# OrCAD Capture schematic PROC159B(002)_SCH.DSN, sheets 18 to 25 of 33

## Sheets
18 01. TABLE OF CONTENTS: title: TABLE OF CONTENTS
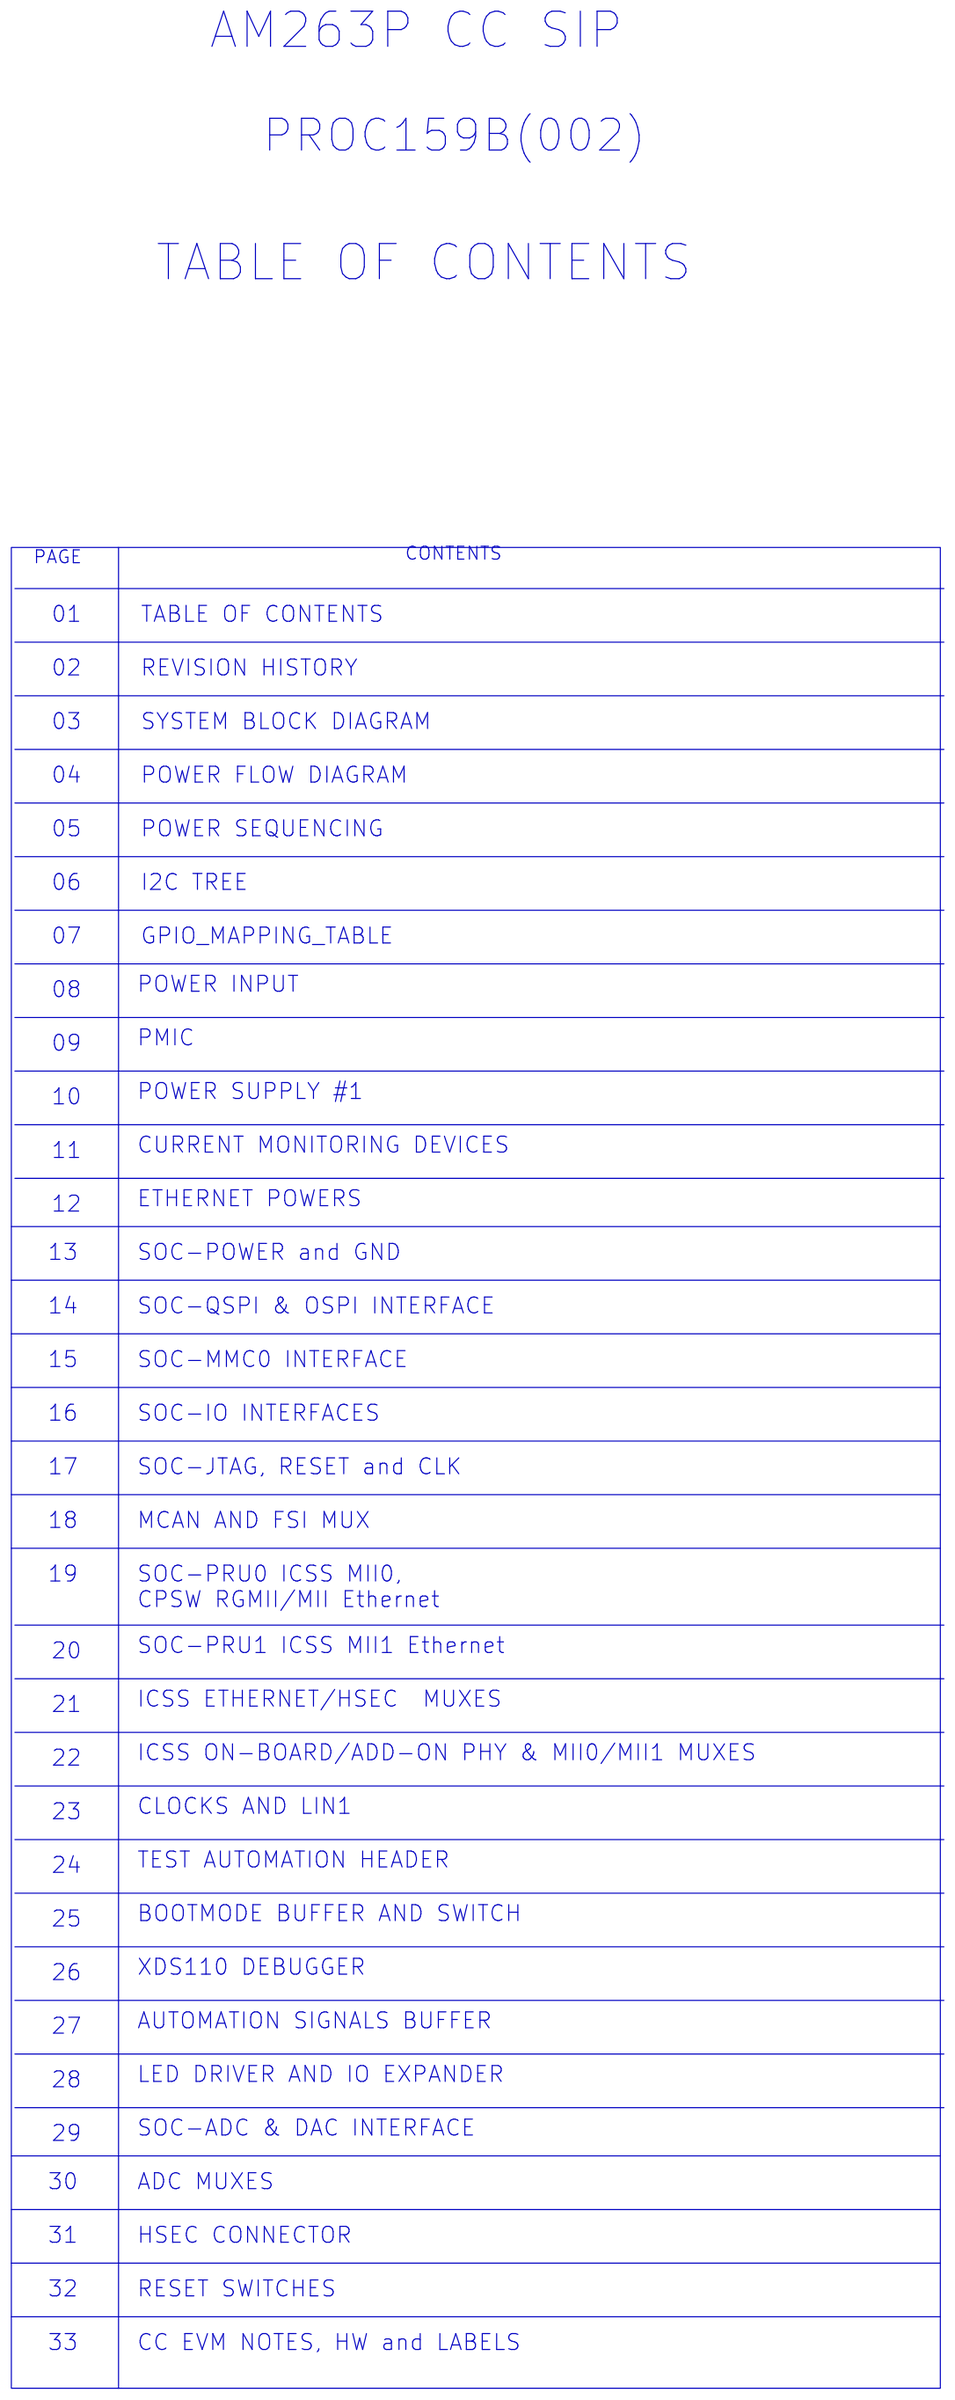
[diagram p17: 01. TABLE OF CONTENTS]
19 02. REVISION HISTORY: title: REVISION HISTORY
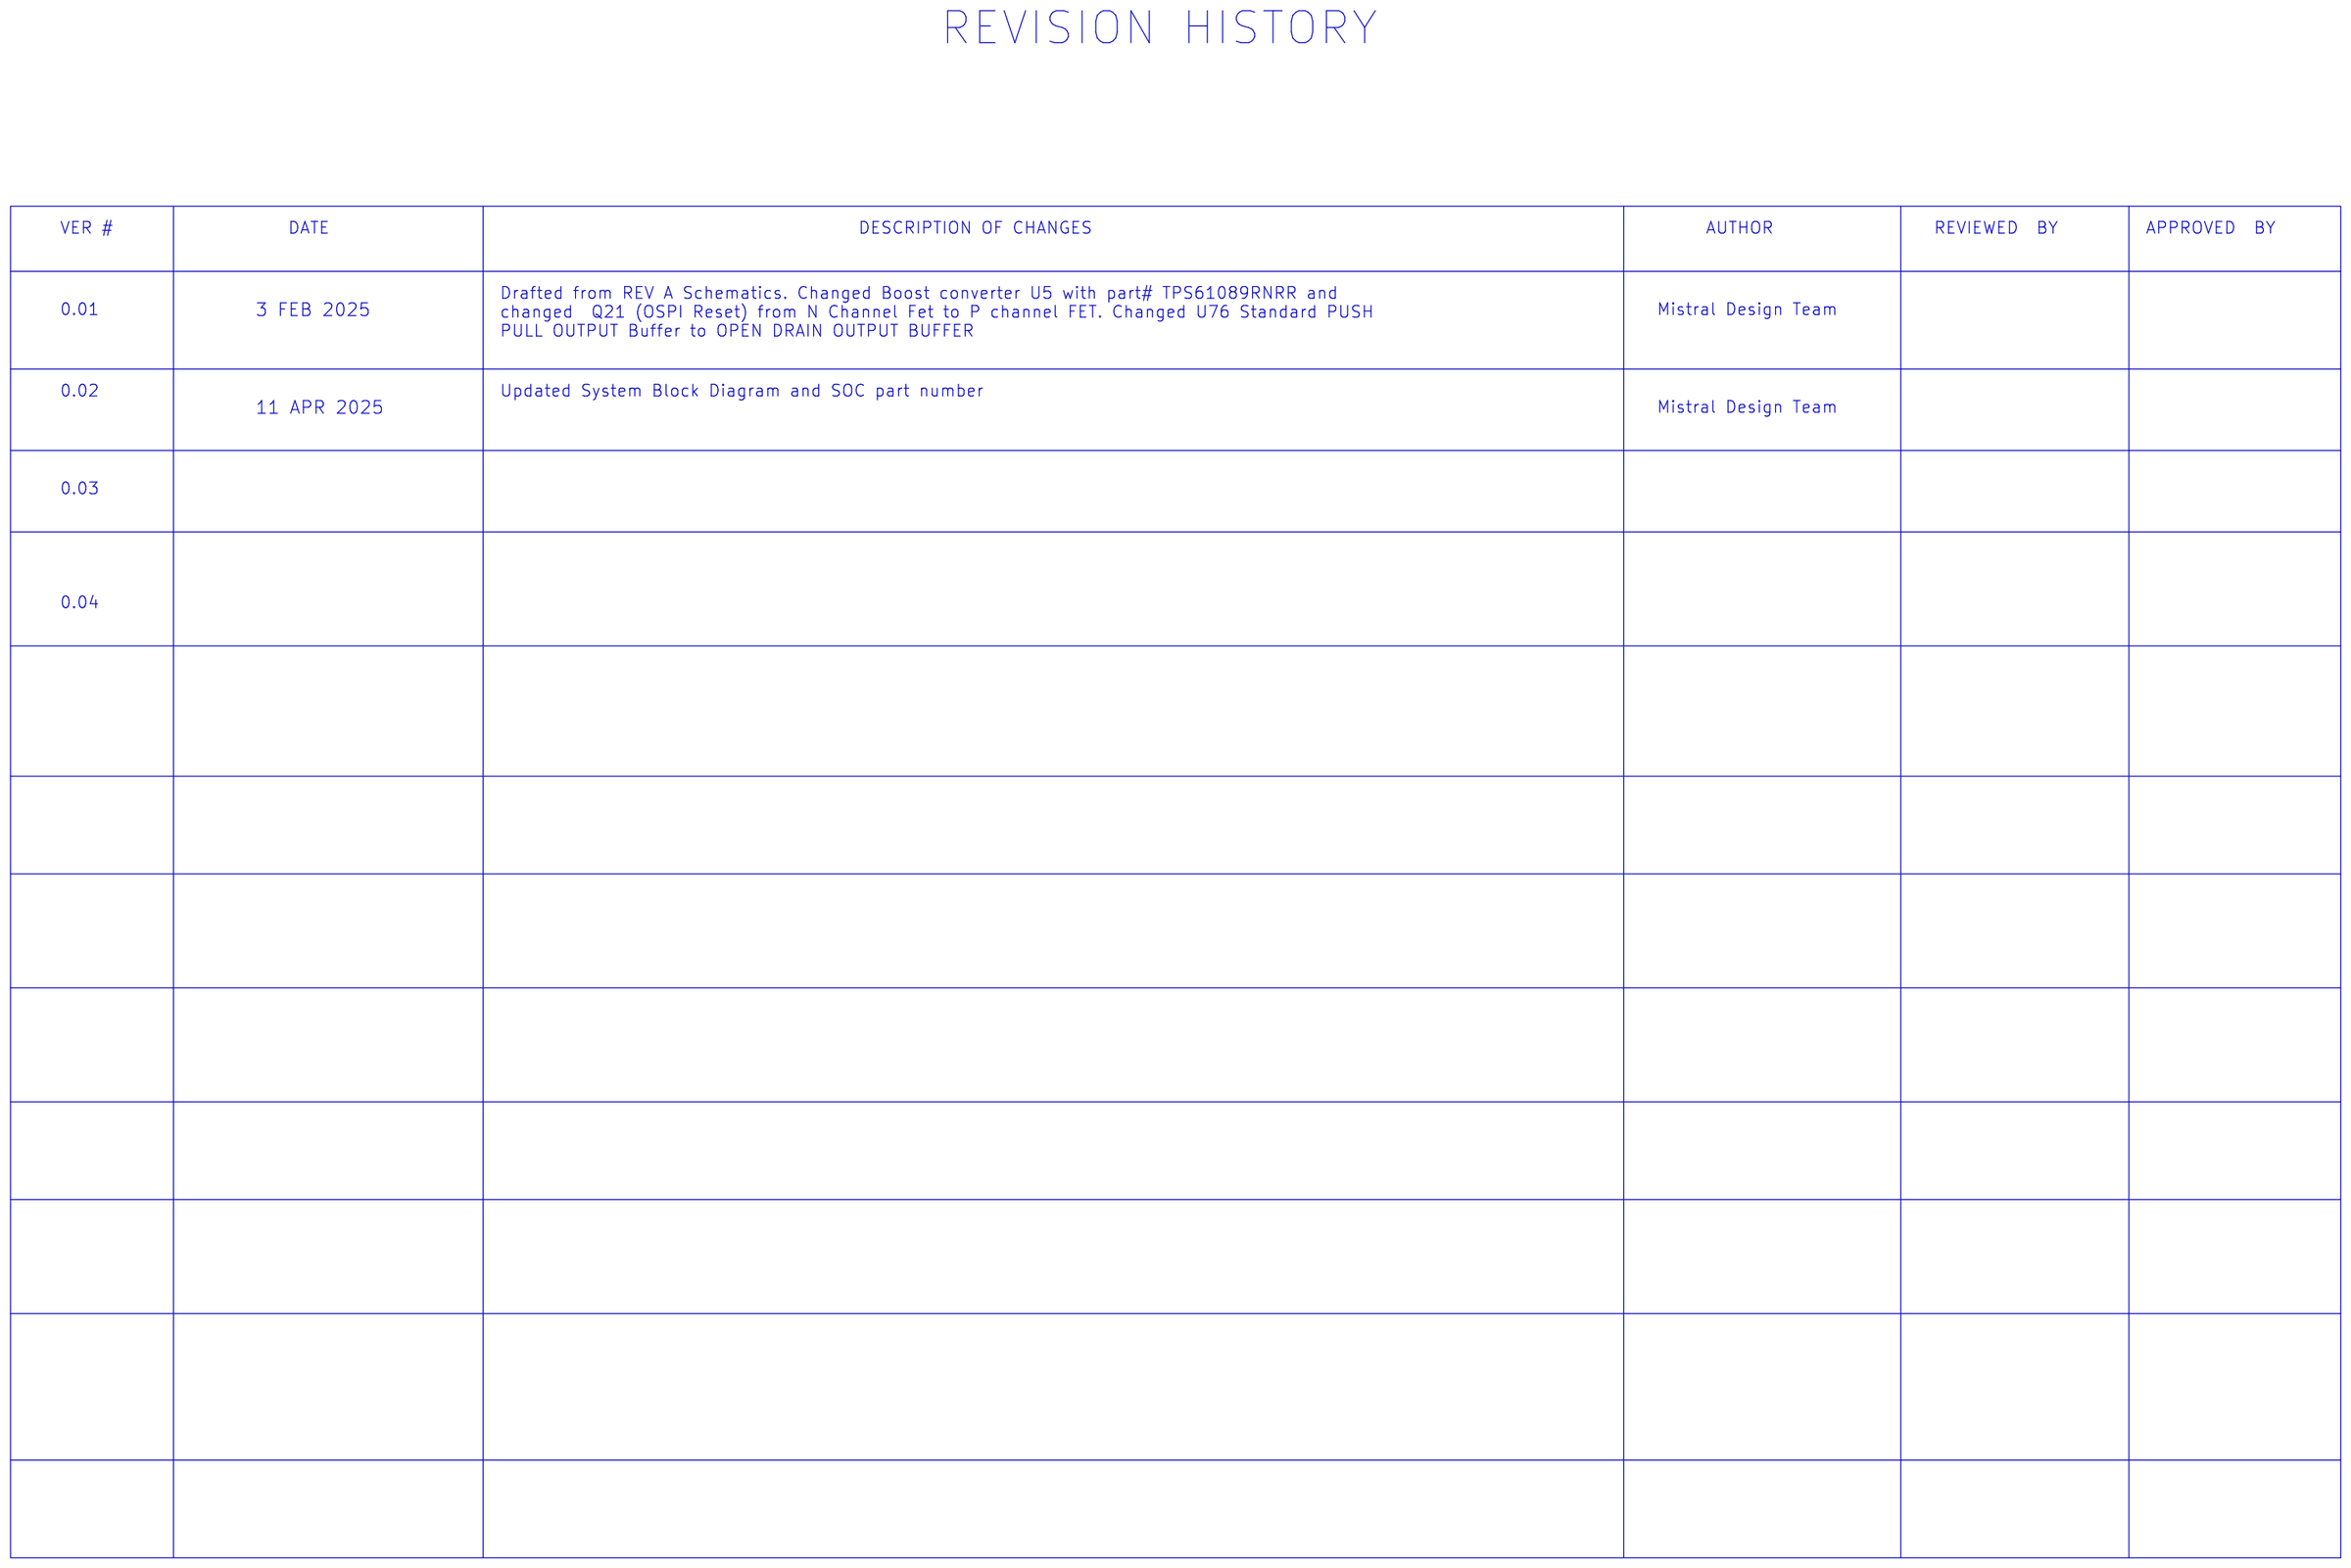
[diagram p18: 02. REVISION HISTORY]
20 03. SYSTEM BLOCK DGM: title: SYSTEM BLOCK DGM
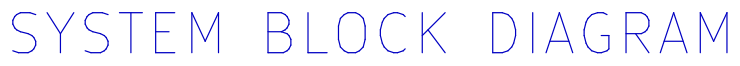
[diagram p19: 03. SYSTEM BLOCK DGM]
21 05. POWER FLOW DIAGRAM: title: POWER FLOW DIAGRAM
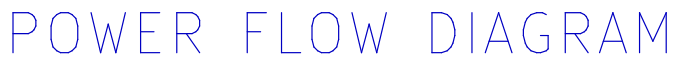
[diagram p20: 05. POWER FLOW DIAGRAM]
22 06. I2C TREE: title: I2C TREE DIAGRAM
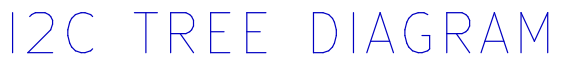
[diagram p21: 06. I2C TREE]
23 07. GPIO_MAPPING_TABLE: title: GPIO MAPPING TABLE
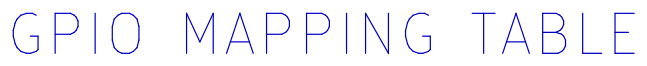
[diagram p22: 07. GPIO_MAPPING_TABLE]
24 14. SOC - QSPI & OSPI Interface: size C; title: SOC - QSPI & OSPI Interface
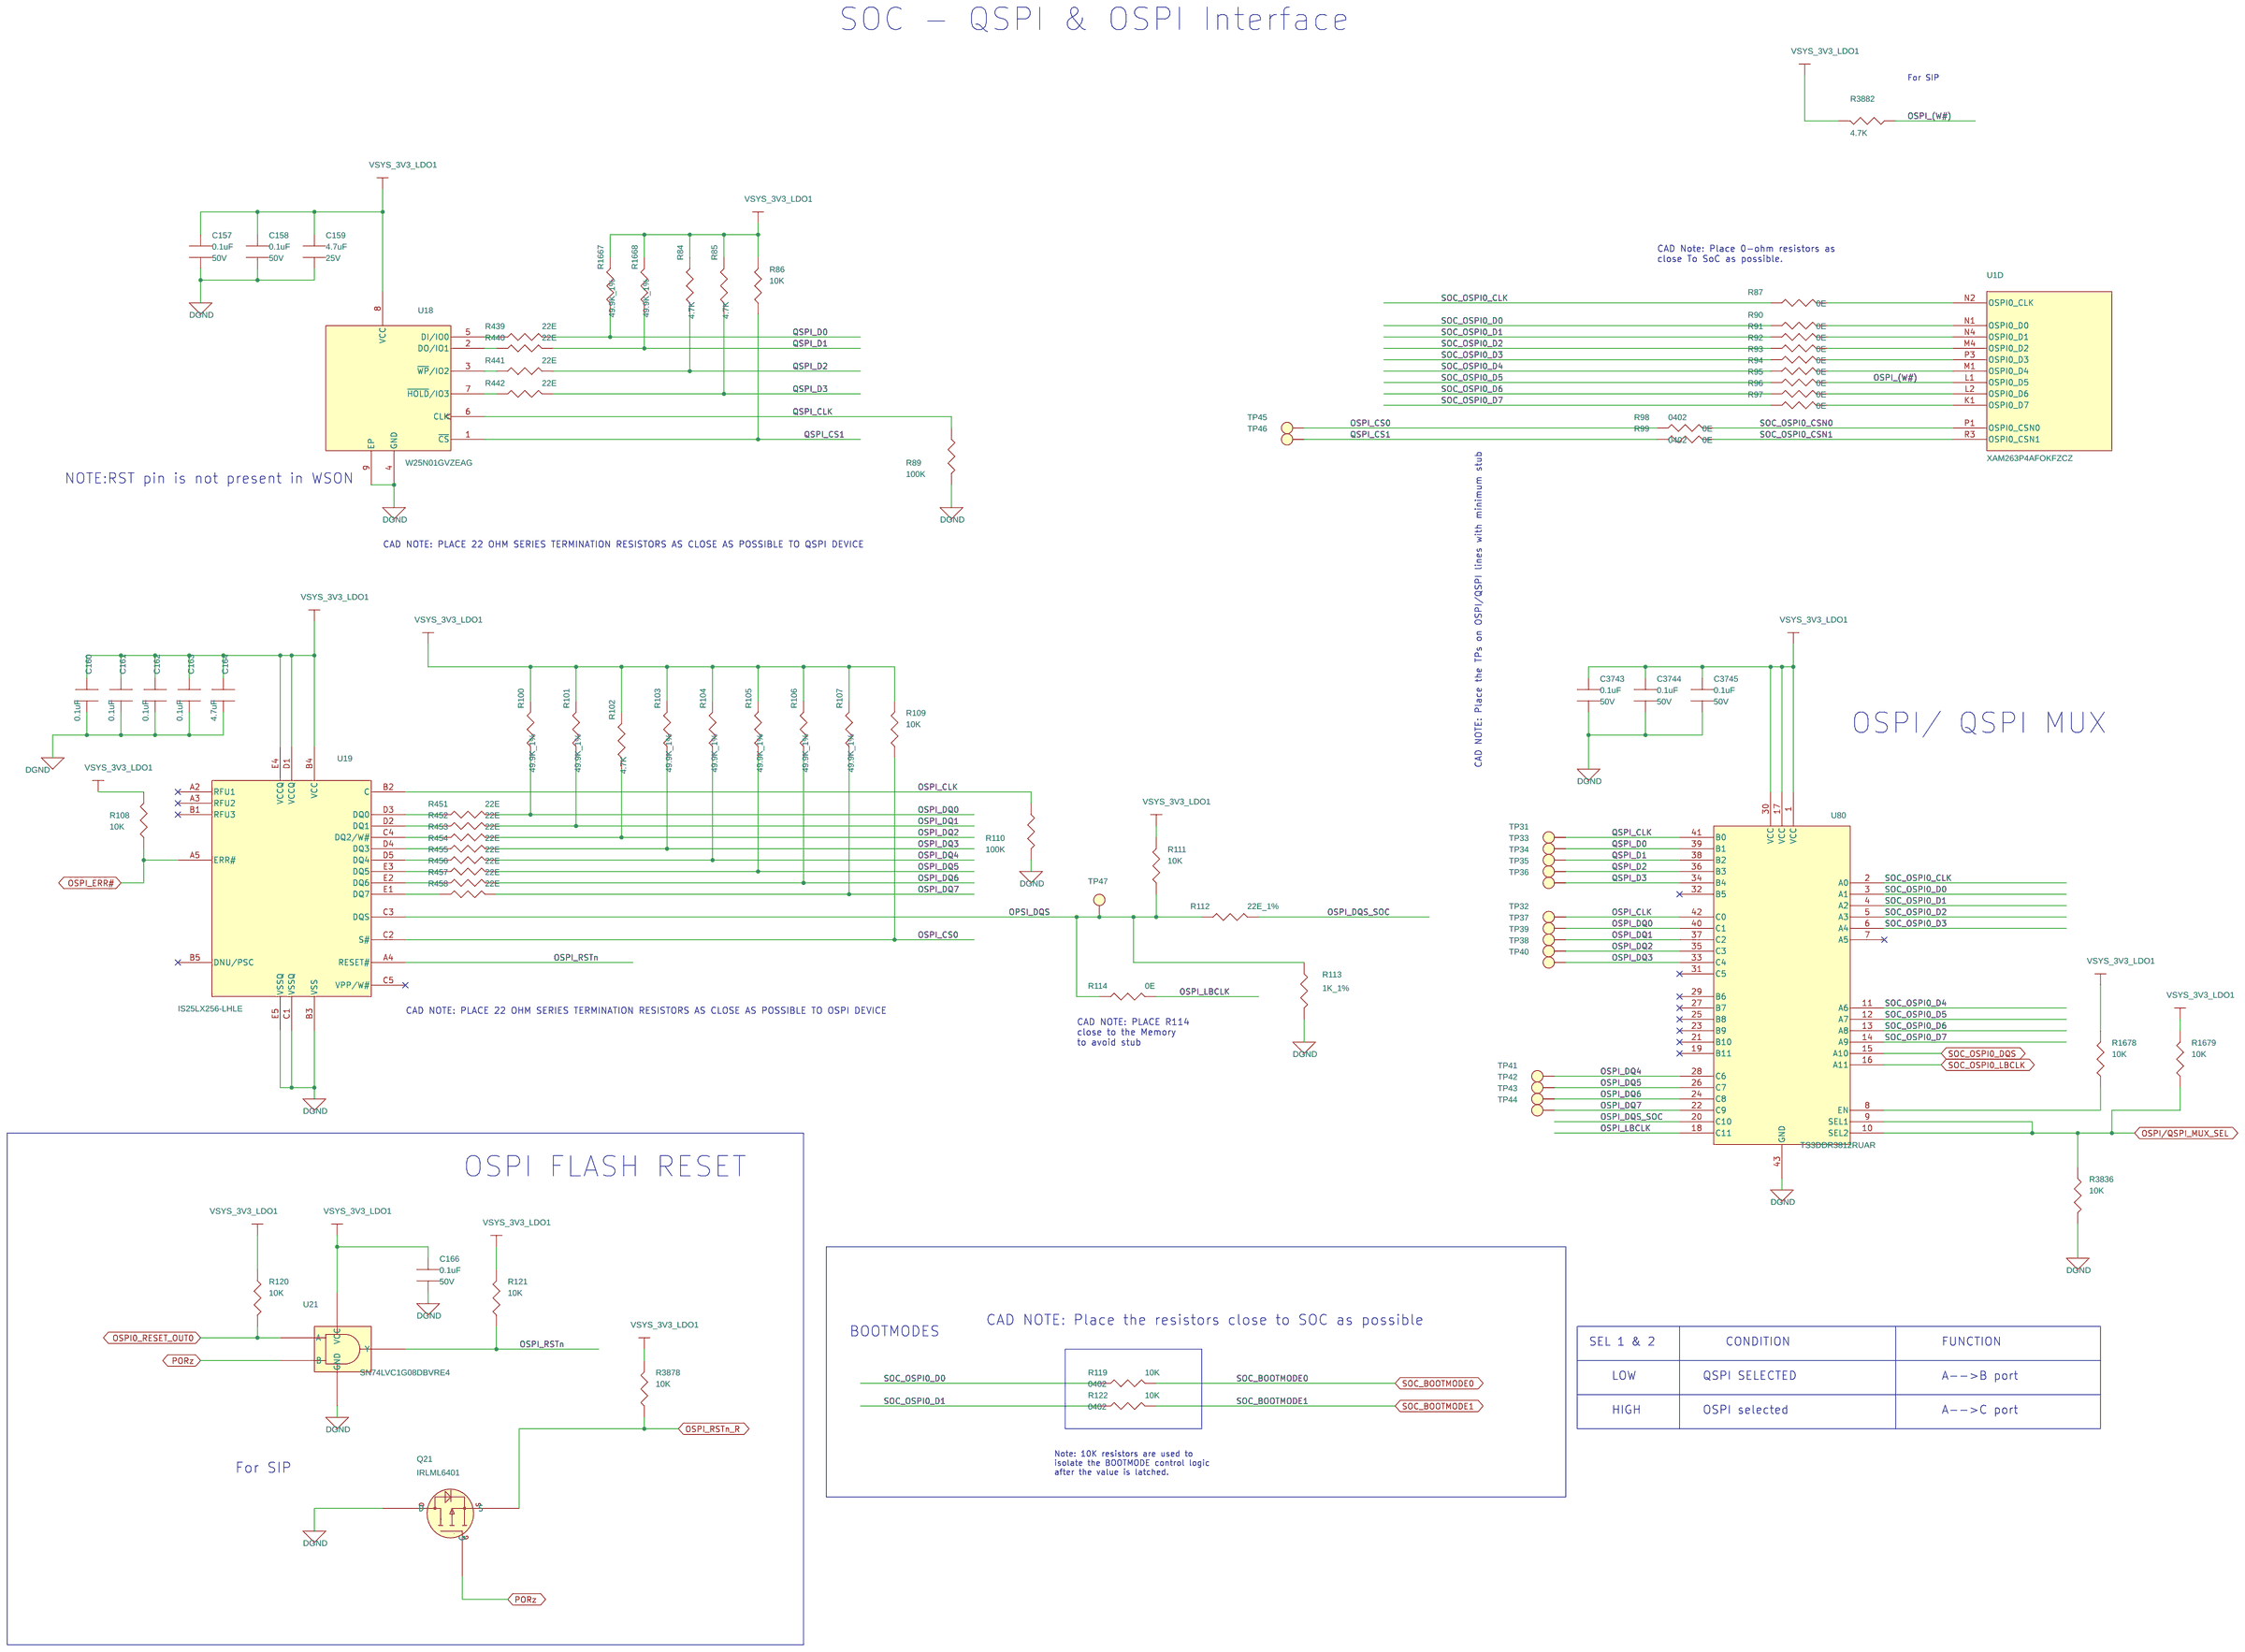
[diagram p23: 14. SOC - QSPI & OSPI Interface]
25 15. SOC-MMC0 Interface: size C; title: SOC- MMC0 Interface
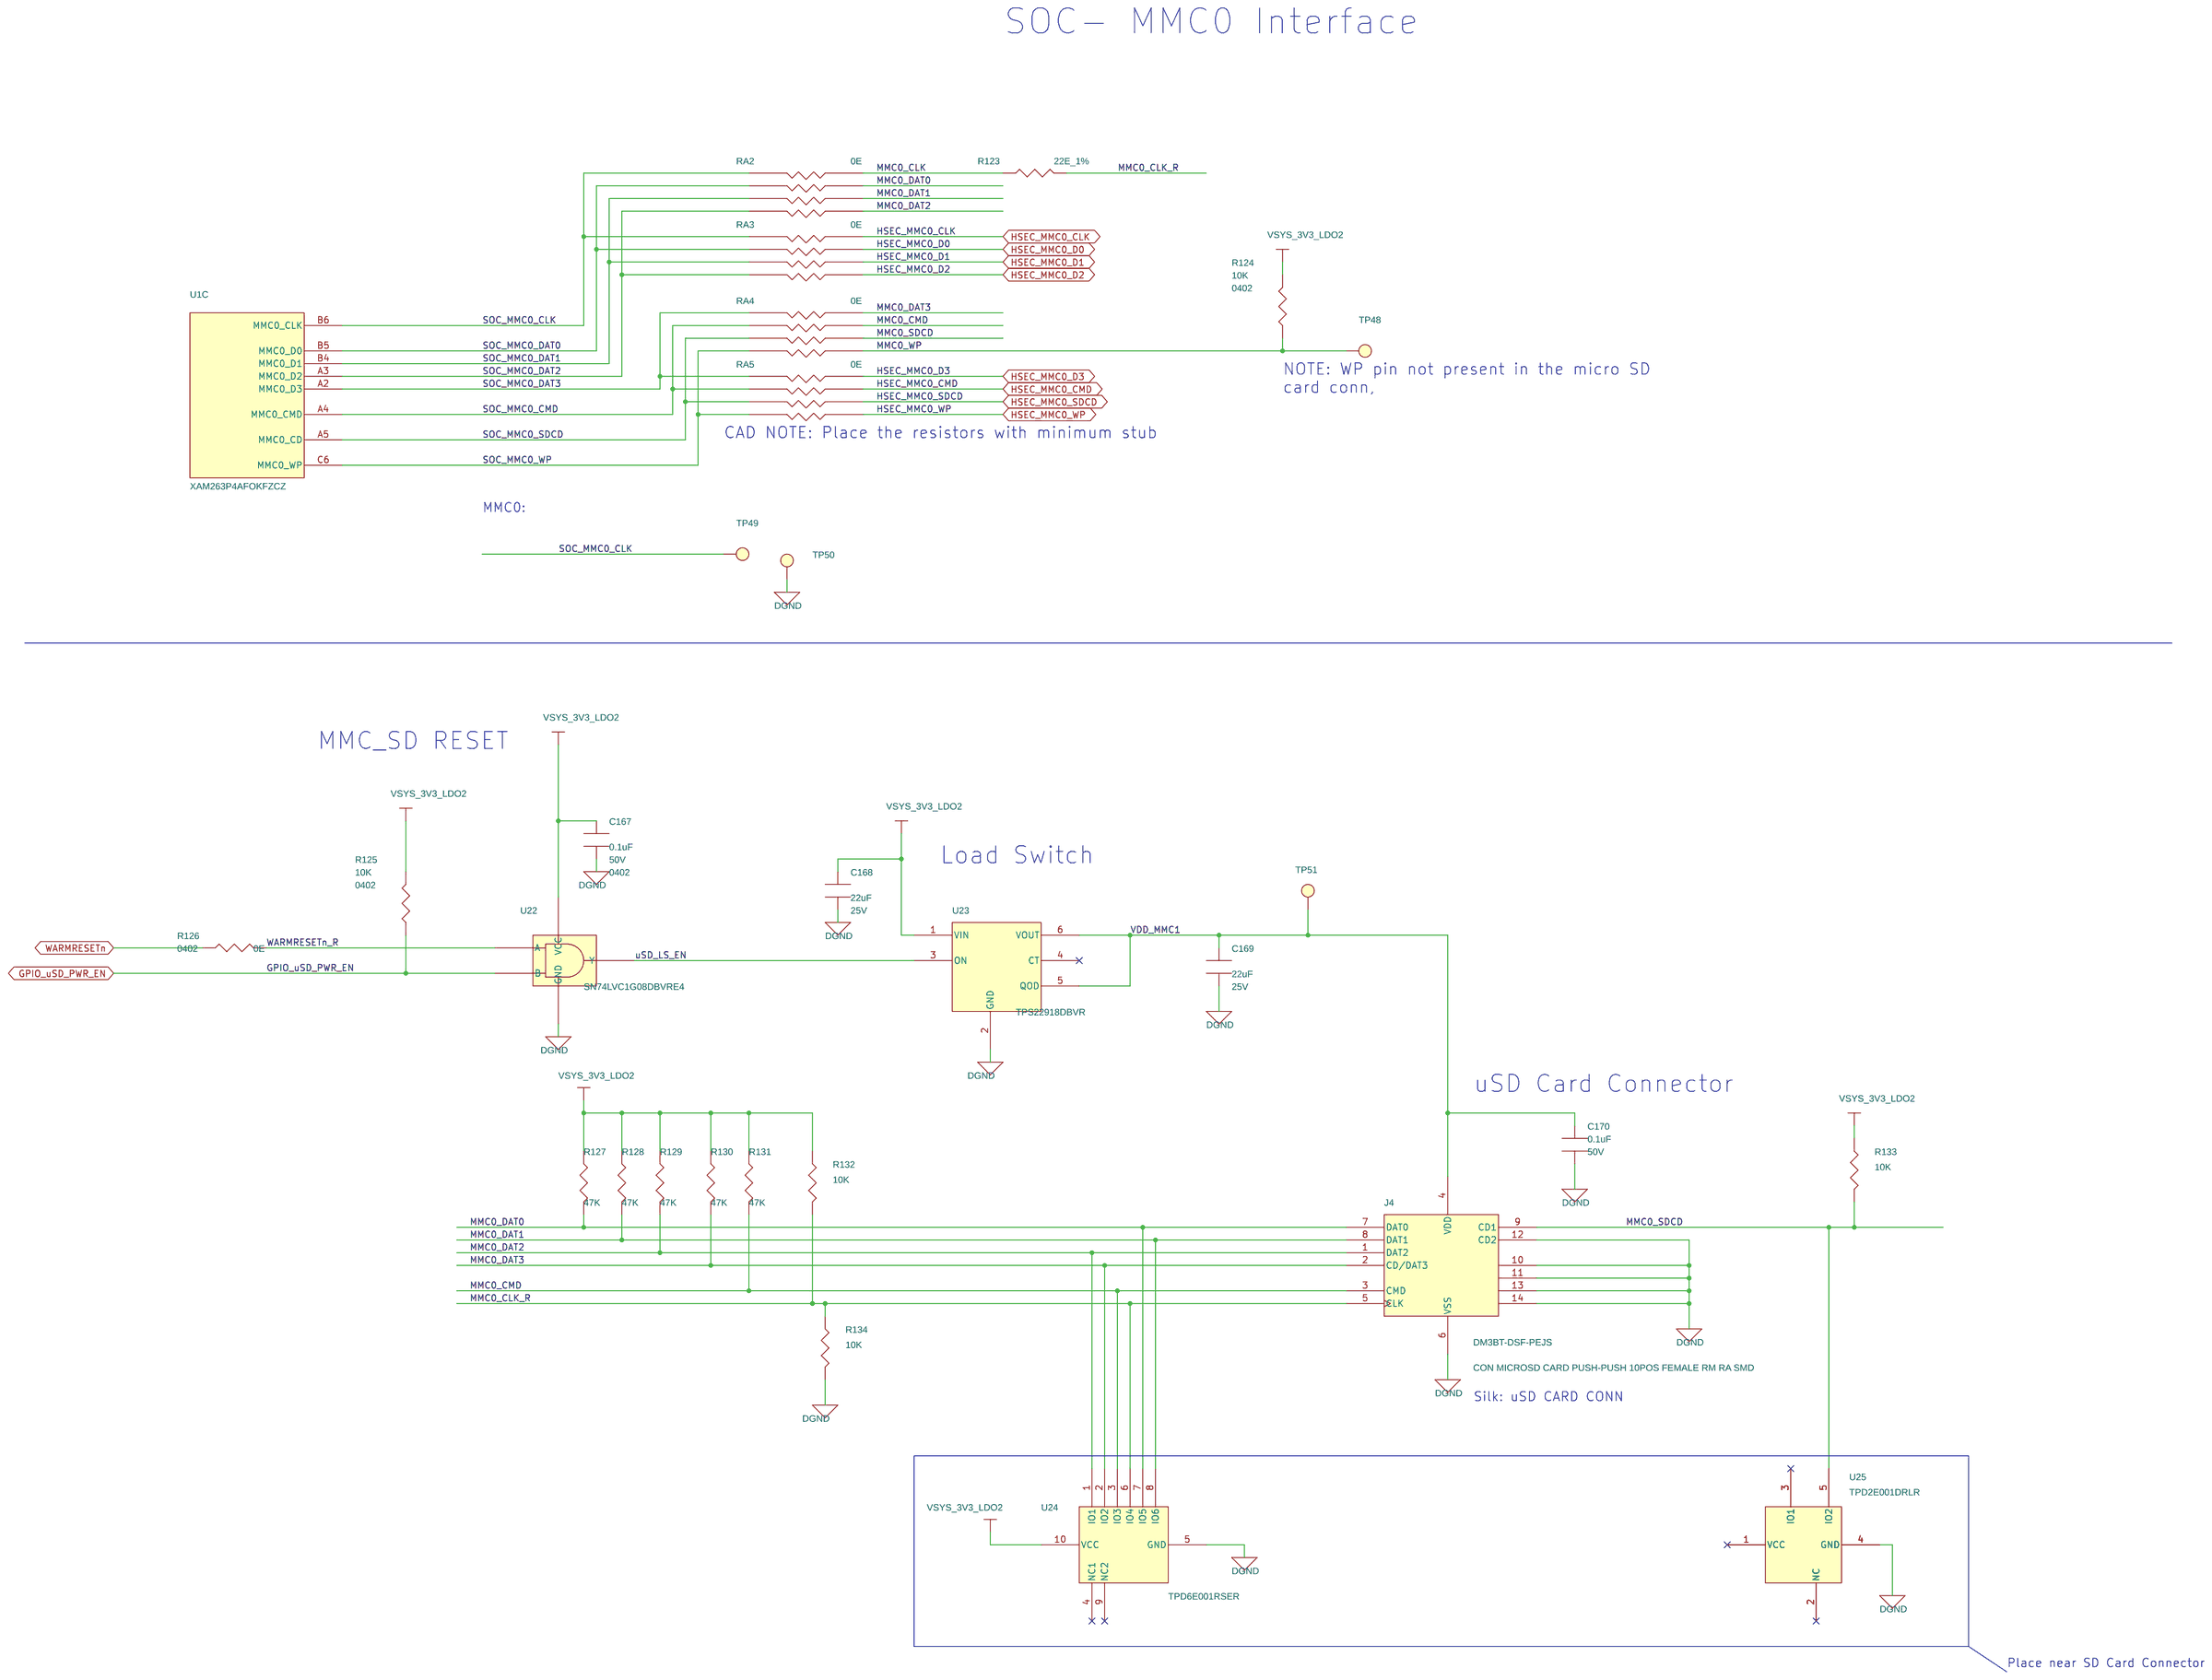
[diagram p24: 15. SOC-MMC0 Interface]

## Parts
sheet 14. SOC - QSPI & OSPI Interface
C157  0.1uF  [CAP0402_0-75]
C158  0.1uF  [CAP0402_0-75]
C159  4.7uF  [CAP0603_1]
C160  0.1uF  [CAP0402_0-75]
C161  0.1uF  [CAP0402_0-75]
C162  0.1uF  [CAP0402_0-75]
C163  0.1uF  [CAP0402_0-75]
C164  4.7uF  [CAP0402_0-75]
C166  0.1uF  [CAP0402_0-75]
C3743  0.1uF  [CAP0402_0-75]
C3744  0.1uF  [CAP0402_0-75]
C3745  0.1uF  [CAP0402_0-75]
Q21  IRLML6401  [TO_SOT23-123]
R84  4.7K  [RES0402_0-5]
R85  4.7K  [RES0402_0-5]
R86  10K  [RES0402_0-5]
R87  0E  [RES0402_0-5]
R89  100K  [RES0201_0-5]
R90  0E  [RES0402_0-5]
R91  0E  [RES0402_0-5]
R92  0E  [RES0402_0-5]
R93  0E  [RES0402_0-5]
R94  0E  [RES0402_0-5]
R95  0E  [RES0402_0-5]
R96  0E  [RES0402_0-5]
R97  0E  [RES0402_0-5]
R98  0E  [RES0402_0-5]
R99  0E  [RES0402_0-5]
R100  49.9K_1%  [RES0402_0-5]
R101  49.9K_1%  [RES0402_0-5]
R102  4.7K  [RES0402_0-5]
R103  49.9K_1%  [RES0402_0-5]
R104  49.9K_1%  [RES0402_0-5]
R105  49.9K_1%  [RES0402_0-5]
R106  49.9K_1%  [RES0402_0-5]
R107  49.9K_1%  [RES0402_0-5]
R108  10K  [RES0201_0-5]
R109  10K  [RES0402_0-5]
R110  100K  [RES0201_0-5]
R111  10K  [RES0201_0-5]
R112  22E_1%  [RES0201_0-5]
R113  1K_1%  [RES0402_0-5]
R114  0E  [RES0201_0-5]
R119  10K  [RES0402_0-5]
R120  10K  [RES0402_0-5]
R121  10K  [RES0201_0-5]
R122  10K  [RES0402_0-5]
R439  22E  [RES0402_0-5]
R440  22E  [RES0402_0-5]
R441  22E  [RES0402_0-5]
R442  22E  [RES0402_0-5]
R451  22E  [RES0402_0-5]
R452  22E  [RES0402_0-5]
R453  22E  [RES0402_0-5]
R454  22E  [RES0402_0-5]
R455  22E  [RES0402_0-5]
R456  22E  [RES0402_0-5]
R457  22E  [RES0402_0-5]
R458  22E  [RES0402_0-5]
R1667  49.9K_1%  [RES0402_0-5]
R1668  49.9K_1%  [RES0402_0-5]
R1678  10K  [RES0201_0-5]
R1679  10K  [RES0201_0-5]
R3836  10K  [RES0402_0-5]
R3878  10K  [RES0201_0-5]
R3882  4.7K  [RES0402_0-5]
TP31  TP20_SMD  [TP20_SMD]
TP32  TP20_SMD  [TP20_SMD]
TP33  TP20_SMD  [TP20_SMD]
TP34  TP20_SMD  [TP20_SMD]
TP35  TP20_SMD  [TP20_SMD]
TP36  TP20_SMD  [TP20_SMD]
TP37  TP20_SMD  [TP20_SMD]
TP38  TP20_SMD  [TP20_SMD]
TP39  TP20_SMD  [TP20_SMD]
TP40  TP20_SMD  [TP20_SMD]
TP41  TP20_SMD  [TP20_SMD]
TP42  TP20_SMD  [TP20_SMD]
TP43  TP20_SMD  [TP20_SMD]
TP44  TP20_SMD  [TP20_SMD]
TP45  TP40_SMD  [TP40_SMD]
TP46  TP40_SMD  [TP40_SMD]
TP47  TP20_SMD  [TP20_SMD]
U18  W25N01GVZEAG  [WSON8_49-99_320X240_0-8]
U19  IS25LX256-LHLE  [TPBGA24_39-37_240X320_1-2]
U21  SN74LVC1G08DBVRE4  [SOT23-5]
U80  TS3DDR3812RUAR  [TQFN42_19-68_140X360_0-8]
sheet 15. SOC-MMC0 Interface
C167  0.1uF  [CAP0402_0-75]
C168  22uF  [CAP0805_1-5]
C169  22uF  [CAP0805_1-5]
C170  0.1uF  [CAP0402_0-75]
J4  CON_SDCARD10_DM3BT-DSF-PEJS  [CON_SD10_DM3BT-DSF-PEJS_S_R_S_2-4]
R123  22E_1%  [RES0402_0-5]
R124  10K  [RES0402_0-5]
R125  10K  [RES0402_0-5]
R126  0E  [RES0402_0-5]
R127  47K  [RES0402_0-5]
R128  47K  [RES0402_0-5]
R129  47K  [RES0402_0-5]
R130  47K  [RES0402_0-5]
R131  47K  [RES0402_0-5]
R132  10K  [RES0402_0-5]
R133  10K  [RES0402_0-5]
R134  10K  [RES0402_0-5]
RA2  0E  [RESA_EXB28V_0402-4_0-5]
RA3  0E  [RESA_EXB28V_0402-4_0-5]
RA4  0E  [RESA_EXB28V_0402-4_0-5]
RA5  0E  [RESA_EXB28V_0402-4_0-5]
TP48  TP30_SMD  [TP30_SMD]
TP49  TP30_SMD  [TP30_SMD]
TP50  TP30_SMD  [TP30_SMD]
TP51  TP40_SMD  [TP40_SMD]
U22  SN74LVC1G08DBVRE4  [SOT23-5]
U23  TPS22918DBVR  [SOT23-6]
U24  TPD6E001RSER  [UQFN10_19-68_80X60_0-6]
U25  TPD2E001DRLR  [SOT553-5_0-6]
sheet 19. SOC-ICSS DP8386(Indust)
U1  XAM263P4AFOKFZCZ  [BGA324_31-49_590X590_1-4]  (sections A,B,C,D,E,F,G,H,I,J,K,L,M)

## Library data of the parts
C157 C158 C167 C3743-C3745 = CAP: CAP CERAMIC 0.1uF 50V 10% X7R 0402; Chkd/date: MANIRAJA/261020; Crtd /date: ALVY/211020; Custom_Duty: 15%; Customs_HS_Code: 85322990; Distributor_name: DIGIKEY; Distributor_part_number: 490-10700-1-ND; Footprint Path: Y:\MIS_DATABASE\Library\ALTIUM_TOOL\PCB_FOOTPRINTS\Altium_Footprint_Lib.PcbLib; Height: 0.55MM; Library Path: Y:\MIS_DATABASE\Library\ALTIUM_TOOL\SCHEMATICS_PARTS\MS_DISCRETE_Library.schlib; Mfr_name: MURATA; Mfr_part_number: GRM155R71H104KE14D; Mistral Part No: 120011100014-R; Package: 0402; Part_type: CAPACITORS\CERAMIC; Project: J7_CP; RoHS: RoHS; Temperature: -55°C+125°C; Tolerance: 10%; Voltage: 50V; Wattage: NA; Weight: 3.1mg; Datasheet: Y:\MIS_DATABASE\DATASHEETS\CAPACITORS\GRM155R71H104KE14.PDF
C159 = CAP: CAP CERAMIC 4.7uF 25V 10% X6S 0603; Chkd/date: MANIRAJA/241018; Crtd /date: ALVY/241018; Custom_Duty: 15%; Customs_HS_Code: 85322990; Distributor_name: DIGIKEY; Distributor_part_number: 490-7199-1-ND; Footprint Path: Y:\MIS_DATABASE\Library\ALTIUM_TOOL\PCB_FOOTPRINTS\Altium_Footprint_Lib.PcbLib; Height: 1.00MM; Library Path: Y:\MIS_DATABASE\Library\ALTIUM_TOOL\SCHEMATICS_PARTS\MS_DISCRETE_Library.schlib; Mfr_name: MURATA; Mfr_part_number: GRM188C81E475KE11D; Mistral Part No: 120018100056-R; Package: 0603; Part_type: CAPACITORS\CERAMIC; Project: TI_J7ES_EVM_CP; RoHS: RoHS; Temperature: -55°C+105°C; Tolerance: 10%; Voltage: 25V; Wattage: NA; Weight: 6.3mg; Datasheet: Y:\MIS_DATABASE\DATASHEETS\CAPACITORS\GRM188C81E475KE11D.PDF
C160-C163 = CAP: CAP CERAMIC 0.1uF 50V 10% X7R 0402; Alt_Mfr_name: YAGEO AMERICA; Alt_Mfr_part_number: CC0402KRX5R8BB104; Chkd/date: MANIRAJA/261020; Crtd /date: ALVY/211020; Custom_Duty: 15%; Customs_HS_Code: 85322990; Distributor_name: DIGIKEY; Distributor_part_number: 490-10700-1-ND; Footprint Path: Y:\MIS_DATABASE\Library\ALTIUM_TOOL\PCB_FOOTPRINTS\Altium_Footprint_Lib.PcbLib; Height: 0.55MM; Library Path: Y:\MIS_DATABASE\Library\ALTIUM_TOOL\SCHEMATICS_PARTS\MS_DISCRETE_Library.schlib; Mfr_name: MURATA; Mfr_part_number: GRM155R71H104KE14D; Mistral Part No: 120011100014-R; Package: 0402; Part_type: CAPACITORS\CERAMIC; Project: J7_CP; RoHS: RoHS; Temperature: -55°C+125°C; Tolerance: 10%; Voltage: 50V; Wattage: NA; Weight: 3.1mg; Datasheet: Y:\MIS_DATABASE\DATASHEETS\CAPACITORS\GRM155R71H104KE14.PDF
C164 = CAP: CAP CERAMIC 4.7uF 10V 20% X5R 0402; Chkd/date: MANIRAJA/110718; Crtd /date: ALVY/110718; Custom_Duty: 15%; Customs_HS_Code: 85322990; Distributor_name: DIGIKEY; Distributor_part_number: 490-14306-1-ND; Footprint Path: Y:\MIS_DATABASE\Library\ALTIUM_TOOL\PCB_FOOTPRINTS\Altium_Footprint_Lib.PcbLib; Height: 0.65MM; Library Path: Y:\MIS_DATABASE\Library\ALTIUM_TOOL\SCHEMATICS_PARTS\MS_DISCRETE_Library.schlib; Mfr_name: MURATA; Mfr_part_number: GRM155R61A475MEAAD; Mistral Part No: 120012060002-R; Package: 0402; Part_type: CAPACITORS\CERAMIC; Project: TI_J7SVB_PCIE_ADD-ON-CARD; RoHS: RoHS; Temperature: -55°C+85°C; Tolerance: 20%; Voltage: 10V; Wattage: NA; Weight: 14mg; Datasheet: Y:\MIS_DATABASE\DATASHEETS\CAPACITORS\GRM155R61A475MEAAD.PDF
C166 C170 = CAP: CAP CERAMIC 0.1uF 50V 10% X7R 0402; Automotive Alternate_mfr_name: TDK; Automotive Alternate_mfr_part_number: CGA2B3X7R1H104K050BB; Chkd/date: MANIRAJA/261020; Crtd /date: ALVY/211020; Custom_Duty: 15%; Customs_HS_Code: 85322990; Direct Alternate_mfr_name: TDK; Direct Alternate_mfr_part_number: C1005X7R1H104K050BE; Distributor_name: DIGIKEY; Distributor_part_number: 490-10700-1-ND; Footprint Path: Y:\MIS_DATABASE\Library\ALTIUM_TOOL\PCB_FOOTPRINTS\Altium_Footprint_Lib.PcbLib; Height: 0.55MM; Library Path: Y:\MIS_DATABASE\Library\ALTIUM_TOOL\SCHEMATICS_PARTS\MS_DISCRETE_Library.schlib; Mfr_name: MURATA; Mfr_part_number: GRM155R71H104KE14D; Mistral Part No: 120011100014-R; Package: 0402; Part_type: CAPACITORS\CERAMIC; Project: J7_CP; RoHS: RoHS; Temperature: -55°C+125°C; Tolerance: 10%; Voltage: 50V; Wattage: NA; Weight: 3.1mg; Datasheet: Y:\MIS_DATABASE\DATASHEETS\CAPACITORS\GRM155R71H104KE14.PDF
Q21 = MOSFET_IRLML6401TR: TRANSISTOR MOSFET P-CHANNEL SOT23-3; Chkd/date: SHREESHAIL/020206; Crtd /date: MAZHAR/040505; Custom_Duty: 15%; Customs_HS_Code: 85412900; Distributor_name: DIGIKEY; Distributor_part_number: IRLML6401PBFCT-ND; Height: 1.11MM; Mfr_name: IRF; Mfr_part_number: IRLML6401TRPBF; Mistral Part No: 130009031213-P; Package: SOT23-3; Part_type: TRANSISTOR\MOSFET; Project: G4_SVGA; RoHS: Pb-Free; Temperature: -55°C+150°C; Tolerance: NA; Voltage: NA; Wattage: NA; Weight: NA; Datasheet: Y:\MIS_DATABASE\DATASHEETS\DISCRETES\TRANSISTORS_FETS\IRLML6401.PDF
R84 R85 R102 R3882 = RESISTOR: RES 4.7K 1/10W 5% 0402; Chkd/date: VASANTHA/201216; Crtd /date: GEETHA/190406; Custom_Duty: 15%; Customs_HS_Code: 85332119; Distributor_name: DIGIKEY; Distributor_part_number: P4.7KJCT-ND; Footprint Path: Y:\MIS_DATABASE\Library\ALTIUM_TOOL\PCB_FOOTPRINTS\Altium_Footprint_Lib.PcbLib; Height: 0.40MM; Library Path: Y:\MIS_DATABASE\Library\ALTIUM_TOOL\SCHEMATICS_PARTS\MS_DISCRETE_Library.schlib; Mfr_name: PANASONIC-ECG; Mfr_part_number: ERJ-2GEJ472X; Mistral Part No: 110009030792-R; Package: 0402; Part_type: RESISTORS\FIXED; Project: RED EYE; RoHS: RoHS; Temperature: -55°C+155°C; Tolerance: 5%; Voltage: NA; Wattage: 1/10W; Weight: 0.8mg; Datasheet: Y:\MIS_DATABASE\DATASHEETS\RESISTORS\PAN-ERJSER_NOV17.PDF
R86 R109 R119 R120 R122 R124 R125 R132-R134 = RESISTOR: RES 10K 1/16W 5% 0402; Chkd/date: VASANTHA/061216; Crtd /date: MAZHAR/230805; Custom_Duty: 15%; Customs_HS_Code: 85332119; Distributor_name: DIGIKEY; Distributor_part_number: 311-10KJRCT-ND; Footprint Path: Y:\MIS_DATABASE\Library\ALTIUM_TOOL\PCB_FOOTPRINTS\Altium_Footprint_Lib.PcbLib; Height: 0.40MM; Library Path: Y:\MIS_DATABASE\Library\ALTIUM_TOOL\SCHEMATICS_PARTS\MS_DISCRETE_Library.schlib; Mfr_name: YAGEO AMERICA; Mfr_part_number: RC0402JR-0710KL; Mistral Part No: 110011060021-R; Package: 0402; Part_type: RESISTORS\FIXED; Project: HSE; RoHS: RoHS; Temperature: -55°C+155°C; Tolerance: 5%; Voltage: NA; Wattage: 1/16W; Weight: 0.65mg; Datasheet: Y:\MIS_DATABASE\DATASHEETS\RESISTORS\RCXXXXL-SER_MAR18.PDF
R87 R90-R99 R126 = RESISTOR: RES 0E 1/10W JUMPER 0402; Chkd/date: VASANTHA/061216; Crtd /date: NAVEED/201014; Custom_Duty: 15%; Customs_HS_Code: 85332119; Distributor_name: DIGIKEY; Distributor_part_number: P0.0JCT-ND; Footprint Path: Y:\MIS_DATABASE\Library\ALTIUM_TOOL\PCB_FOOTPRINTS\Altium_Footprint_Lib.PcbLib; Height: 0.40MM; IBISSP_MODLES: VALUE REPEATING 2 TIME; Library Path: Y:\MIS_DATABASE\Library\ALTIUM_TOOL\SCHEMATICS_PARTS\MS_DISCRETE_Library.schlib; Mfr_name: PANASONIC-ECG; Mfr_part_number: ERJ-2GE0R00X; Mistral Part No: 110018030052-R; Package: 0402; Part_type: RESISTORS\FIXED; Project: AEGIS POM; RoHS: RoHS; Temperature: -55°C+155°C; Tolerance: NA; Voltage: NA; Wattage: 1/10W; Weight: 0.8mg; Datasheet: Y:\MIS_DATABASE\DATASHEETS\RESISTORS\PAN-ERJSER_NOV17.PDF
R89 R110 = RESISTOR: RES 100K 1/20W 5% 0201; Chkd/date: MANIRAJA/050517; Crtd /date: MANIRAJA/050517; Custom_Duty: 15%; Customs_HS_Code: 85332119; Distributor_name: DIGIKEY; Distributor_part_number: 311-100KNCT-ND; Footprint Path: Y:\MIS_DATABASE\Library\ALTIUM_TOOL\PCB_FOOTPRINTS\Altium_Footprint_Lib.PcbLib; Height: 0.26MM; Library Path: Y:\MIS_DATABASE\Library\ALTIUM_TOOL\SCHEMATICS_PARTS\MS_DISCRETE_Library.schlib; Mfr_name: YAGEO AMERICA; Mfr_part_number: RC0201JR-07100KL; Mistral Part No: 110009030176-R; Package: 0201; Part_type: RESISTORS\FIXED; Project: GOLDEN-I LITE; RoHS: RoHS; Temperature: -55°C+125°C; Tolerance: 5%; Voltage: NA; Wattage: 1/20W; Weight: 0.17mg; Datasheet: Y:\MIS_DATABASE\DATASHEETS\RESISTORS\RCXXXXL-SER_MAR18.PDF
R100 R101 R103-R107 R1667 R1668 = RESISTOR: RES 49.9K 1/10W 1% 0402; Chkd/date: MANIRAJA/130617; Crtd /date: BAVISH/020611; Custom_Duty: 15%; Customs_HS_Code: 85332119; Distributor_name: DIGIKEY; Distributor_part_number: P49.9KLCT-ND; Footprint Path: Y:\MIS_DATABASE\Library\ALTIUM_TOOL\PCB_FOOTPRINTS\Altium_Footprint_Lib.PcbLib; Height: 0.40MM; Library Path: Y:\MIS_DATABASE\Library\ALTIUM_TOOL\SCHEMATICS_PARTS\MS_DISCRETE_Library.schlib; Mfr_name: PANASONIC-ECG; Mfr_part_number: ERJ-2RKF4992X; Mistral Part No: 110011060018-R; Package: 0402; Part_type: RESISTORS\FIXED; Project: AM4515_EVM_LCD; RoHS: RoHS; Temperature: -55°C+155°C; Tolerance: 1%; Voltage: NA; Wattage: 1/10W; Weight: 0.8mg; Datasheet: Y:\MIS_DATABASE\DATASHEETS\RESISTORS\PAN-ERJSER_NOV17.PDF
R108 R111 R121 R1678 R1679 R3878 = RESISTOR: RES 10K 1/20W 5% 0201; Chkd/date: MANIRAJA/050517; Crtd /date: MANIRAJA/050517; Custom_Duty: 15%; Customs_HS_Code: 85332119; Distributor_name: DIGIKEY; Distributor_part_number: 311-10KNCT-ND; Footprint Path: Y:\MIS_DATABASE\Library\ALTIUM_TOOL\PCB_FOOTPRINTS\Altium_Footprint_Lib.PcbLib; Height: 0.26MM; Library Path: Y:\MIS_DATABASE\Library\ALTIUM_TOOL\SCHEMATICS_PARTS\MS_DISCRETE_Library.schlib; Mfr_name: YAGEO AMERICA; Mfr_part_number: RC0201JR-0710KL; Mistral Part No: 110010070051-R; Package: 0201; Part_type: RESISTORS\FIXED; Project: GOLDEN-I LITE; RoHS: RoHS; Temperature: -55°C+125°C; Tolerance: 5%; Voltage: NA; Wattage: 1/20W; Weight: 0.17mg; Datasheet: Y:\MIS_DATABASE\DATASHEETS\RESISTORS\RCXXXXL-SER_MAR18.PDF
R112 = RESISTOR: RES 22E 1/20W 1% 0201; Chkd/date: PRAVEEN/080922; Crtd /date: TAMILARASU/080922; Custom_Duty: 15%; Customs_HS_Code: 85332119; Distributor_name: DIGIKEY; Distributor_part_number: P122843CT-ND; Footprint Path: Y:\MIS_DATABASE\Library\ALTIUM_TOOL\PCB_FOOTPRINTS\Altium_Footprint_Lib.PcbLib; Height: 0.26MM; Library Path: Y:\MIS_DATABASE\Library\ALTIUM_TOOL\SCHEMATICS_PARTS\MS_DISCRETE_Library.schlib; Mfr_name: PANASONIC-ECG; Mfr_part_number: ERJ-1GNF22R0C; Mistral Part No: 110022090007-R; Package: 0201; Part_type: RESISTORS\FIXED; Project: SK AM62Q LP EVM BRD; RoHS: RoHS; SIGNAL_MODEL: RESISTOR_RES0201_0-5_22E_1%_22E_1%; Temperature: -55°C+125°C; Tolerance: 1%; Voltage: NA; Wattage: 1/20W; Weight: 0.15mg; Datasheet: Y:\MIS_DATABASE\DATASHEETS\RESISTORS\PAN-ERJSER_NOV17.PDF
R113 = RESISTOR: RES 1K 1/10W 1% 0402; Chkd/date: VASANTHA/281216; Crtd /date: MAZHAR/150506; Custom_Duty: 15%; Customs_HS_Code: 85332119; Distributor_name: DIGIKEY; Distributor_part_number: P1.00KLCT-ND; Footprint Path: Y:\MIS_DATABASE\Library\ALTIUM_TOOL\PCB_FOOTPRINTS\Altium_Footprint_Lib.PcbLib; Height: 0.40MM; Library Path: Y:\MIS_DATABASE\Library\ALTIUM_TOOL\SCHEMATICS_PARTS\MS_DISCRETE_Library.schlib; Mfr_name: PANASONIC-ECG; Mfr_part_number: ERJ-2RKF1001X; Mistral Part No: 110009030411-R; Package: 0402; Part_type: RESISTORS\FIXED; Project: VOCERA; RoHS: RoHS; Temperature: -55°C+155°C; Tolerance: 1%; Voltage: NA; Wattage: 1/10W; Weight: 0.8mg; Datasheet: Y:\MIS_DATABASE\DATASHEETS\RESISTORS\PAN-ERJSER_NOV17.PDF
R114 = RESISTOR: RES 0E 1/20W 5% 0201; Chkd/date: NAVEED/301214; Crtd /date: MUDDU/120710; Custom_Duty: 15%; Customs_HS_Code: 85332119; Distributor_name: DIGIKEY; Distributor_part_number: 311-0.0NCT-ND; Footprint Path: Y:\MIS_DATABASE\Library\ALTIUM_TOOL\PCB_FOOTPRINTS\Altium_Footprint_Lib.PcbLib; Height: 0.26MM; Library Path: Y:\MIS_DATABASE\Library\ALTIUM_TOOL\SCHEMATICS_PARTS\MS_DISCRETE_Library.schlib; Mfr_name: YAGEO AMERICA; Mfr_part_number: RC0201JR-070RL; Mistral Part No: 110010070067-R; Package: 0201; Part_type: RESISTORS\FIXED; Project: PB_BUGBASE; RoHS: RoHS; SIGNAL_MODEL: RESISTOR_RES0201_0-5_0E_0E; Temperature: -55°C+125°C; Tolerance: 5%; Voltage: NA; Wattage: 1/20W; Weight: 0.17mg; Datasheet: Y:\MIS_DATABASE\DATASHEETS\RESISTORS\RCXXXXL-SER_MAR18.PDF
R439-R442 R451-R458 = RESISTOR: RES 22E 1/10W 5% 0402; Chkd/date: VASANTHA/060117; Crtd /date: MAZHAR/120505; Custom_Duty: 15%; Customs_HS_Code: 85332119; Distributor_name: DIGIKEY; Distributor_part_number: P22JCT-ND; Footprint Path: Y:\MIS_DATABASE\Library\ALTIUM_TOOL\PCB_FOOTPRINTS\Altium_Footprint_Lib.PcbLib; Height: 0.40MM; Library Path: Y:\MIS_DATABASE\Library\ALTIUM_TOOL\SCHEMATICS_PARTS\MS_DISCRETE_Library.schlib; Mfr_name: PANASONIC-ECG; Mfr_part_number: ERJ-2GEJ220X; Mistral Part No: 110009030515-R; Package: 0402; Part_type: RESISTORS\FIXED; Project: EPDA_CORE; RoHS: RoHS; Temperature: -55°C+155°C; Tolerance: 5%; Voltage: NA; Wattage: 1/10W; Weight: 0.8mg; Datasheet: Y:\MIS_DATABASE\DATASHEETS\RESISTORS\PAN-ERJSER_NOV17.PDF
R3836 = RESISTOR: RES 10K 1/16W 5% 0402; Assembly_Instruction: DNI; Chkd/date: VASANTHA/061216; Crtd /date: MAZHAR/230805; Custom_Duty: 15%; Customs_HS_Code: 85332119; Distributor_name: DIGIKEY; Distributor_part_number: 311-10KJRCT-ND; Footprint Path: Y:\MIS_DATABASE\Library\ALTIUM_TOOL\PCB_FOOTPRINTS\Altium_Footprint_Lib.PcbLib; Height: 0.40MM; Library Path: Y:\MIS_DATABASE\Library\ALTIUM_TOOL\SCHEMATICS_PARTS\MS_DISCRETE_Library.schlib; Mfr_name: YAGEO AMERICA; Mfr_part_number: RC0402JR-0710KL; Mistral Part No: 110011060021-R; Package: 0402; Part_type: RESISTORS\FIXED; Project: HSE; RoHS: RoHS; Temperature: -55°C+155°C; Tolerance: 5%; Voltage: NA; Wattage: 1/16W; Weight: 0.65mg; Datasheet: Y:\MIS_DATABASE\DATASHEETS\RESISTORS\RCXXXXL-SER_MAR18.PDF
TP31-TP44 TP47 = TESTPOINT: TESTPOINT CIR 20 SMD; Chkd/date: SHREESHAIL/171006; Crtd /date: MAZHAR/171006; Custom_Duty: NA; Customs_HS_Code: NA; Distributor_name: NA; Distributor_part_number: NA; Footprint Path: Y:\MIS_DATABASE\Library\ALTIUM_TOOL\PCB_FOOTPRINTS\Altium_Footprint_Lib.PcbLib; Height: NA; Library Path: Y:\MIS_DATABASE\Library\ALTIUM_TOOL\SCHEMATICS_PARTS\MS_DISCRETE_Library.schlib; MECHANICAL 3D STEP FILE: NA; Mfr_name: LOCAL; Mistral Part No: NA; Package: SMD; Project: BT MODULE_CSRBC04; RoHS: NA; Temperature: NA; Tolerance: NA; Voltage: NA; Wattage: NA; Weight: NA; Datasheet: NA
TP45 TP46 TP51 = TESTPOINT: TESTPOINT CIR 40 SMD; Chkd/date: MAZHAR/190505; Crtd /date: MAZHAR/190505; Distributor_name: NA; Distributor_part_number: NA; Footprint Path: Y:\MIS_DATABASE\Library\ALTIUM_TOOL\PCB_FOOTPRINTS\Altium_Footprint_Lib.PcbLib; Height: NA; Library Path: Y:\MIS_DATABASE\Library\ALTIUM_TOOL\SCHEMATICS_PARTS\MS_DISCRETE_Library.schlib; MECHANICAL 3D STEP FILE: NA; Mfr_name: LOCAL; Mistral Part No: 130009030933; Package: SMD; Project: RAINIER-3; RoHS: NA; Temperature: NA; Tolerance: NA; Voltage: NA; Wattage: NA; Weight: NA; Datasheet: NA
U18 = W25N01GVZEIG_WSON8: IC 1GBIT SERIAL NAND FLASH MEMORY WITH DUQL/QUAD SPI BUFFER WSON8; Chkd/date: PRAVEEN/150323; Crtd /date: TAMILARASU/140323; Custom_Duty: 15%; Customs_HS_Code: 85423100; Distributor_name: NA; Distributor_part_number: NA; Footprint Path: Y:\MIS_DATABASE\Library\ALTIUM_TOOL\PCB_FOOTPRINTS\Altium_Footprint_Lib.PcbLib; Height: 0.80MM; Library Path: Y:\MIS_DATABASE\Library\ALTIUM_TOOL\SCHEMATICS_PARTS\MS_MISCMEMORY_Library.schlib; MECHANICAL 3D STEP FILE: WSON8_49-99_310X240_0-8; Mfr_name: WINBOND; Mistral Part No: 141023030006-R; Package: WSON8; Part_type: ICS\DIGITAL\MEMORY; Project: AM263P CC; RoHS: RoHS; Temperature: -40°C+85°C; Tolerance: NA; Voltage: NA; Wattage: NA; Weight: NA; Datasheet: Y:\MIS_DATABASE\DATASHEETS\ICS\MEMORY\W25N01GV.PDF
U19 = IS25LX256_TFBGA24: IC 256Mb 3V 133MHz SERIAL FLASH MEMORY OCTAL I/O xSPI INTERACE WITH ON-CHIP ECC TFBGA24; Chkd/date: PRAVEEN/140623; Crtd /date: PRADEEP/140623; Custom_Duty: 15%; Customs_HS_Code: 85423100; Distributor_name: NA; Distributor_part_number: NA; Footprint Path: Y:\MIS_DATABASE\Library\ALTIUM_TOOL\PCB_FOOTPRINTS\Altium_Footprint_Lib.PcbLib; Height: 1.20MM; Library Path: Y:\MIS_DATABASE\Library\ALTIUM_TOOL\SCHEMATICS_PARTS\MS_MISCMEMORY_Library.schlib; Mfr_name: ISSI; Mistral Part No: 141123060003-R; Package: TFBGA24; Part_type: ICS\DIGITAL\MEMORY; Project: AM263P_CC; RoHS: RoHS; Temperature: -40°C+105°C; Tolerance: NA; Voltage: NA; Wattage: NA; Weight: NA; Datasheet: Y:\MIS_DATABASE\DATASHEETS\ICS\MEMORY\IS25LX256.PDF
U21 U22 = SN74LVC1G08DBVRE4_SOT23-5: IC SINGLE 2-INPUT POSITIVE AND GATE SOT23-5; Automotive Alternate_mfr_name: TEXAS INSTRUMENTS; Automotive Alternate_mfr_part_number: SN74LVC1G08QDBVRQ1; Chkd/date: SUHAS/221010; Crtd /date: USMAN/151008; Custom_Duty: 15%; Customs_HS_Code: 85423100; Distributor_name: DIGIKEY; Distributor_part_number: SN74LVC1G08DBVRE4-ND; Height: 1.45MM; Mfr_name: TEXAS INSTRUMENTS; Mistral Part No: 141009060026-R; Part_type: ICS\DIGITAL\GATES; Project: KHAN_MAIN; RoHS: Sb/ Br FREE; Temperature: -40°C+85°C; Datasheet: Y:\MIS_DATABASE\DATASHEETS\ICS\DIGITAL\GATES\SN74LVC1G08.PDF
U80 = TS3DDR3812RUAR_WQFN42: IC 12-CH 1:2 MUX/DEMUX SWITCH FOR DDR3 APPLICATION WQFN42; Chkd/date: MANIRAJA/250918; Crtd /date: ALVY/250918; Custom_Duty: 15%; Customs_HS_Code: 85423100; Distributor_name: DIGIKEY; Distributor_part_number: 296-28307-1-ND; Footprint Path: Y:\MIS_DATABASE\Library\ALTIUM_TOOL\PCB_FOOTPRINTS\Altium_Footprint_Lib.PcbLib; Height: 0.80MM; Library Path: Y:\MIS_DATABASE\Library\ALTIUM_TOOL\SCHEMATICS_PARTS\MS_COMBINATIONAL_Library.schlib; Mfr_name: TEXAS INSTRUMENTS; Mistral Part No: 141018090023-R; Package: WQFN42; Part_type: ICS\DIGITAL\COMBINATIONAL; Project: TI_J7ES_EVM_CP; RoHS: RoHS; Temperature: -40°C+85°C; Tolerance: NA; Voltage: NA; Wattage: NA; Weight: 54.8mg; Datasheet: Y:\MIS_DATABASE\DATASHEETS\ICS\DIGITAL\COMBINATIONAL\TS3DDR3812.PDF
C168 C169 = CAP: CAP CERAMIC 22uF 25V 20% X5R 0805; Automotive Alternate_mfr_name: MURATA; Automotive Alternate_mfr_part_number: GRT21BR61E226ME13L; Chkd/date: MANIRAJA/110718; Crtd /date: ALVY/110718; Custom_Duty: 15%; Customs_HS_Code: 85322990; Direct Alternate_mfr_name: MURATA; Direct Alternate_mfr_part_number: GRM21BR61E226ME44L; Distributor_name: DIGIKEY; Distributor_part_number: 490-14661-1-ND; Footprint Path: Y:\MIS_DATABASE\Library\ALTIUM_TOOL\PCB_FOOTPRINTS\Altium_Footprint_Lib.PcbLib; Height: 1.45MM; Library Path: Y:\MIS_DATABASE\Library\ALTIUM_TOOL\SCHEMATICS_PARTS\MS_DISCRETE_Library.schlib; Mfr_name: MURATA; Mfr_part_number: GRM21BR61E226ME44K; Mistral Part No: 120013120018-R; Package: 0805; Part_type: CAPACITORS\CERAMIC; Project: TI_J7SVB_PCIE_ADD-ON-CARD; RoHS: RoHS; Temperature: -55°C+85°C; Tolerance: 20%; Voltage: 25V; Wattage: NA; Weight: 9.5mg; Datasheet: Y:\MIS_DATABASE\DATASHEETS\CAPACITORS\GRM21BR61E226ME44K.PDF
J4 = CON_SDCARD_10_DM3BT-DSF-PEJS: CON MICROSD CARD PUSH-PUSH 10POS FEMALE RM RA SMD; Chkd/date: MANIRAJA/080218; Crtd /date: BAVISH/190111; Custom_Duty: 24%; Customs_HS_Code: 85369090; Distributor_name: DIGIKEY; Distributor_part_number: HR1942CT-ND; Footprint Path: Y:\MIS_DATABASE\Library\ALTIUM_TOOL\PCB_FOOTPRINTS\Altium_Footprint_Lib.PcbLib; Height: 2.38MM; Library Path: Y:\MIS_DATABASE\Library\ALTIUM_TOOL\SCHEMATICS_PARTS\MS_CONNECTOR_Library.schlib; Mfr_name: HIROSE ELECTRIC; Mfr_part_number: DM3BT-DSF-PEJS; Mistral Part No: 150011010020-R; Package: SMD; Part_type: CONNECTOR\MEMORY CARD; Project: EBOOK; RoHS: RoHS; Temperature: -25°C+85°C; Tolerance: NA; Voltage: NA; Wattage: NA; Weight: 1.315g; Datasheet: Y:\MIS_DATABASE\DATASHEETS\CONNECTORS\DM3-SERIES.PDF
R123 = RESISTOR: RES 22E 1/10W 1% 0402; Chkd/date: MANIRAJA/270319; Crtd /date: MANIRAJA/270319; Custom_Duty: 15%; Customs_HS_Code: 85332119; Distributor_name: DIGIKEY; Distributor_part_number: P22.0LCT-ND; Footprint Path: Y:\MIS_DATABASE\Library\ALTIUM_TOOL\PCB_FOOTPRINTS\Altium_Footprint_Lib.PcbLib; Height: 0.40MM; Library Path: Y:\MIS_DATABASE\Library\ALTIUM_TOOL\SCHEMATICS_PARTS\MS_DISCRETE_Library.schlib; Mfr_name: PANASONIC-ECG; Mfr_part_number: ERJ-2RKF22R0X; Mistral Part No: 110019040025-R; Package: 0402; Part_type: RESISTORS\FIXED; Project: V8TS; RoHS: RoHS; Temperature: -55°C+155°C; Tolerance: 1%; Voltage: NA; Wattage: 1/10W; Weight: 0.8mg; Datasheet: Y:\MIS_DATABASE\DATASHEETS\RESISTORS\PAN-ERJSER_NOV17.PDF
R127-R131 = RESISTOR: RES 47K 1/10W 5% 0402; Chkd/date: VASANTHA/281216; Crtd /date: MAZHAR/120505; Custom_Duty: 15%; Customs_HS_Code: 85332119; Distributor_name: DIGIKEY; Distributor_part_number: P47KJCT-ND; Footprint Path: Y:\MIS_DATABASE\Library\ALTIUM_TOOL\PCB_FOOTPRINTS\Altium_Footprint_Lib.PcbLib; Height: 0.40MM; Library Path: Y:\MIS_DATABASE\Library\ALTIUM_TOOL\SCHEMATICS_PARTS\MS_DISCRETE_Library.schlib; Mfr_name: PANASONIC-ECG; Mfr_part_number: ERJ-2GEJ473X; Mistral Part No: 110009030882-R; Package: 0402; Part_type: RESISTORS\FIXED; Project: CTP02_REVA_BASE; RoHS: RoHS; Temperature: -55°C+155°C; Tolerance: 5%; Voltage: NA; Wattage: 1/10W; Weight: 0.8mg; Datasheet: Y:\MIS_DATABASE\DATASHEETS\RESISTORS\PAN-ERJSER_NOV17.PDF
RA2-RA5 = RESARR_ISO4: RES ARRAY 0E 1/16W JUMPER 0402-4; Chkd/date: SUHAS/270910; Crtd /date: MAZHAR/051009; Custom_Duty: 15%; Customs_HS_Code: 85332119; Distributor_name: DIGIKEY; Distributor_part_number: Y7000CT-ND; Footprint Path: Y:\MIS_DATABASE\Library\ALTIUM_TOOL\PCB_FOOTPRINTS\Altium_Footprint_Lib.PcbLib; Height: 0.45MM; Library Path: Y:\MIS_DATABASE\Library\ALTIUM_TOOL\SCHEMATICS_PARTS\MS_DISCRETE_Library.schlib; Mfr_name: PANASONIC-ECG; Mfr_part_number: EXB-28VR000X; Mistral Part No: 110009100001-R; Package: 0402-4; Part_type: RESISTORS\ARRAY; Project: BUG_BASE_PIM; RoHS: RoHS; Temperature: -55°C+125°C; Tolerance: NA; Voltage: NA; Wattage: 1/16W; Weight: 2mg; Datasheet: Y:\MIS_DATABASE\DATASHEETS\RESISTORS\EXB-18V.PDF
TP48-TP50 = TESTPOINT: TESTPOINT CIR 30 SMD; Chkd/date: SHREESHAIL/171006; Crtd /date: MAZHAR/171006; Custom_Duty: NA; Customs_HS_Code: NA; Distributor_name: NA; Distributor_part_number: NA; Footprint Path: Y:\MIS_DATABASE\Library\ALTIUM_TOOL\PCB_FOOTPRINTS\Altium_Footprint_Lib.PcbLib; Height: NA; Library Path: Y:\MIS_DATABASE\Library\ALTIUM_TOOL\SCHEMATICS_PARTS\MS_DISCRETE_Library.schlib; MECHANICAL 3D STEP FILE: NA; Mfr_name: LOCAL; Mistral Part No: 130009030930; Package: SMD; Project: BT MODULE_CSRBC04; RoHS: NA; Temperature: NA; Tolerance: NA; Voltage: NA; Wattage: NA; Weight: NA; Datasheet: NA
U23 = TPS22918DBVR_SOT23-6: IC ON RESISTANCE LOAD SWITCH SOT23-6; Automotive Alternate_mfr_name: TEXAS INSTRUMENTS; Automotive Alternate_mfr_part_number: TPS22918TDBVRQ1; Chkd/date: VASANTHA/130516; Crtd /date: VASANTHA/130516; Custom_Duty: 15%; Customs_HS_Code: 85423100; Distributor_name: DIGIKEY; Distributor_part_number: TPS22918DBVR-ND; Height: 1.45MM; Mfr_name: TEXAS INSTRUMENTS; Mistral Part No: 142016050007-R; Part_type: ICS\POWER; Project: TMDXCSK8127; RoHS: RoHS; Temperature: -40°C to 105°C; Tolerance: NA; Voltage: NA; Wattage: NA; Weight: NA; Datasheet: Y:\MIS_DATABASE\DATASHEETS\ICS\POWER\TPS22918DBV.PDF
U24 = TPD6E001RSE_UQFN10: IC 6CH ESD-PROTECTION ARRAY UQFN10; Chkd/date: USMAN/070612; Crtd /date: BAVISH/160811; Custom_Duty: 15%; Customs_HS_Code: 85423100; Distributor_name: DIGIKEY; Distributor_part_number: 296-21888-1-ND; Footprint Path: Y:\MIS_DATABASE\Library\ALTIUM_TOOL\PCB_FOOTPRINTS\Altium_Footprint_Lib.PcbLib; Height: 0.60MM; IBISSP_MODLES: Y:\MIS_DATABASE\IBIS\ICs\INTERFACE\TPD6E001RSE.IBS; Library Path: Y:\MIS_DATABASE\Library\ALTIUM_TOOL\SCHEMATICS_PARTS\MS_MISCINTERFACE_Library.schlib; Mfr_name: TEXAS INSTRUMENTS; Mistral Part No: 141011080020-R; Package: UQFN10; Part_type: ICS\INTERFACE; Project: DM385EVM_BASE-BOARD; RoHS: RoHS; Temperature: -40°C+85°C; Tolerance: NA; Voltage: NA; Wattage: NA; Weight: 7mg; Datasheet: Y:\MIS_DATABASE\DATASHEETS\ICS\INTERFACE\TPD6E001.PDF
U25 = TPD2E001DRLR_SOT-5_1: IC ESD-PROTECTION DIODE ARRAYS SOT-5; Automotive Alternate_mfr_name: TEXAS INSTRUMENTS; Automotive Alternate_mfr_part_number: TPD2E001IDRLRQ1; Chkd/date: NAVEED/150714; Crtd /date: MUDDU/250510; Custom_Duty: 15%; Customs_HS_Code: 85423100; Distributor_name: DIGIKEY; Distributor_part_number: 296-21883-1-ND; Footprint Path: Y:\MIS_DATABASE\Library\ALTIUM_TOOL\PCB_FOOTPRINTS\Altium_Footprint_Lib.PcbLib; Height: 0.60MM; Library Path: Y:\MIS_DATABASE\Library\ALTIUM_TOOL\SCHEMATICS_PARTS\MS_FILTER_Library.schlib; Library Ref: TPD2E001DRLR_SOT-5; Mfr_name: TEXAS INSTRUMENTS; Mistral Part No: 140110060007-R; Package: SOT-5; Part_type: ICS\ANALOG\ACTIVE FILTER; Project: CENTAURUS; RoHS: RoHS; Temperature: -40°C+85°C; Tolerance: NA; Voltage: NA; Wattage: NA; Weight: 2.8mg; Datasheet: Y:\MIS_DATABASE\DATASHEETS\ICS\MISC\TPD2E001DRLR.PDF
U1 = XAM263P4ASOKFZCZ_BGA324: IC SIP AM263P SoC BGA324; Chkd/date: PRADEEP/030124; Crtd /date: PRADEEP/030124; Custom_Duty: 15%; Customs_HS_Code: 85423100; Distributor_name: NA; Distributor_part_number: NA; Footprint Path: Y:\MIS_DATABASE\Library\ALTIUM_TOOL\PCB_FOOTPRINTS\Altium_Footprint_Lib.PcbLib; Height: 1.40MM; MECHANICAL 3D STEP FILE: NA; Mfr_name: TEXAS INSTRUMENTS; Mistral Part No: 141324010001; Package: BGA324; Part_type: ICS\DIGITAL\FPGA; Project: AM263P_CC; RoHS: RoHS; Temperature: NA; Tolerance: NA; Voltage: NA; Wattage: NA; Weight: NA; Datasheet: Y:\MIS_DATABASE\DATASHEETS\ICS\INTERFACE\ZCZ0324A.PDF

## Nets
DGND: C157.2 C158.2 C159.1 C160.2 C161.2 C162.2 C163.2 C164.1 C166.2 C167.2 C168.2 C169.2 C170.2 C3743.2 C3744.2 C3745.2 J4.6(VSS) J4.10 J4.11 J4.12(CD2) J4.13 J4.14 Q21.3(D) R89.2 R110.2 R113.2 R134.2 R3836.2 TP50.1(TP) U18.4(GND) U18.9(EP) U19.B3(VSS) U19.C1(VSSQ) U19.E5(VSSQ) U21.3(GND) U22.3(GND) U23.2(GND) U24.5(GND) U25.4(GND) U80.43(GND) ; also on sheet 1 2 3 4 6 7 8 9 10 11 12 13 14 15 16 17 26 27 28 29 30 32 33
VDD_MMC1: C169.1 C170.1 J4.4(VDD) TP51.1(TP) U23.5(QOD) U23.6(VOUT)
GPIO_uSD_PWR_EN: R125.1 U22.2(B) ; also on sheet 12
HSEC_MMC0_CLK: RA3.4 ; also on sheet 6
HSEC_MMC0_CMD: RA5.3 ; also on sheet 6
HSEC_MMC0_D0: RA3.3 ; also on sheet 6
HSEC_MMC0_D1: RA3.2 ; also on sheet 6
HSEC_MMC0_D2: RA3.1 ; also on sheet 6
HSEC_MMC0_D3: RA5.4 ; also on sheet 6
HSEC_MMC0_SDCD: RA5.2 ; also on sheet 6
HSEC_MMC0_WP: RA5.1 ; also on sheet 6
MMC0_CLK: R123.1 RA2.4
MMC0_CLK_R: J4.5(CLK) R123.2 R132.2 R134.1 U24.6(IO4)
MMC0_CMD: J4.3(CMD) R131.2 RA4.3 U24.3(IO3)
MMC0_DAT0: J4.7(DAT0) R127.2 RA2.3 U24.7(IO5)
MMC0_DAT1: J4.8(DAT1) R128.2 RA2.2 U24.8(IO6)
MMC0_DAT2: J4.1(DAT2) R129.2 RA2.1 U24.1(IO1)
MMC0_DAT3: J4.2(CD/DAT3) R130.2 RA4.4 U24.2(IO2)
MMC0_SDCD: J4.9(CD1) R133.2 RA4.2 U25.5(IO2)
MMC0_WP: R124.1 RA4.1 TP48.1(TP)
OPSI_DQS: R111.1 R112.1 R113.1 R114.1 TP47.1(TP) U19.C3(DQS)
OSPI0_RESET_OUT0: R120.1 U21.1(A) ; also on sheet 27
OSPI/QSPI_MUX_SEL: R1679.1 R3836.1 U80.9(SEL1) U80.10(SEL2) ; also on sheet 12
OSPI_(W#): R95.2 R3882.2 U1.L1(OSPI0_D5)
OSPI_CLK: R110.1 TP32.1(TP) U19.B2(C) U80.42(C0)
OSPI_CS0: R98.1 R109.2 TP45.1(TP) U19.C2(S#)
OSPI_DQ0: R100.1 R451.2 TP37.1(TP) U80.40(C1)
OSPI_DQ1: R101.1 R452.2 TP39.1(TP) U80.37(C2)
OSPI_DQ2: R102.2 R453.2 TP38.1(TP) U80.35(C3)
OSPI_DQ3: R103.1 R454.2 TP40.1(TP) U80.33(C4)
OSPI_DQ4: R104.1 R455.2 TP41.1(TP) U80.28(C6)
OSPI_DQ5: R105.1 R456.2 TP42.1(TP) U80.26(C7)
OSPI_DQ6: R106.1 R457.2 TP43.1(TP) U80.24(C8)
OSPI_DQ7: R107.1 R458.2 TP44.1(TP) U80.22(C9)
OSPI_DQS_SOC: R112.2 U80.20(C10)
OSPI_ERR#: R108.1 U19.A5(ERR#) ; also on sheet 27
OSPI_LBCLK: R114.2 U80.18(C11)
OSPI_RSTn: R121.1 U19.A4(RESET#) U21.4(Y)
OSPI_RSTn_R: Q21.2(S) R3878.1 ; also on sheet 27
PORZ: Q21.1(G) U21.2(B) ; also on sheet 6 7 10 11 15 27
QSPI_CLK: R89.1 TP31.1(TP) U18.6(CLK) U80.41(B0)
QSPI_CS1: R86.2 R99.1 TP46.1(TP) U18.1(~{CS})
QSPI_D0: R439.2 R1667.1 TP33.1(TP) U80.39(B1)
QSPI_D1: R440.2 R1668.1 TP34.1(TP) U80.38(B2)
QSPI_D2: R84.2 R441.2 TP35.1(TP) U80.36(B3)
QSPI_D3: R85.2 R442.2 TP36.1(TP) U80.34(B4)
SOC_BOOTMODE0: R119.2 ; also on sheet 11
SOC_BOOTMODE1: R122.2 ; also on sheet 11
SOC_MMC0_CLK: RA2.5 RA3.5 TP49.1(TP) U1.B6(MMC0_CLK)
SOC_MMC0_CMD: RA4.6 RA5.6 U1.A4(MMC0_CMD)
SOC_MMC0_DAT0: RA2.6 RA3.6 U1.B5(MMC0_D0)
SOC_MMC0_DAT1: RA2.7 RA3.7 U1.B4(MMC0_D1)
SOC_MMC0_DAT2: RA2.8 RA3.8 U1.A3(MMC0_D2)
SOC_MMC0_DAT3: RA4.5 RA5.5 U1.A2(MMC0_D3)
SOC_MMC0_SDCD: RA4.7 RA5.7 U1.A5(MMC0_CD)
SOC_MMC0_WP: RA4.8 RA5.8 U1.C6(MMC0_WP)
SOC_OSPI0_CLK: R87.1 U80.2(A0)
SOC_OSPI0_CSN0: R98.2 U1.P1(OSPI0_CSN0)
SOC_OSPI0_CSN1: R99.2 U1.R3(OSPI0_CSN1)
SOC_OSPI0_D0: R90.1 R119.1 U80.3(A1)
SOC_OSPI0_D1: R91.1 R122.1 U80.4(A2)
SOC_OSPI0_D2: R92.1 U80.5(A3)
SOC_OSPI0_D3: R93.1 U80.6(A4)
SOC_OSPI0_D4: R94.1 U80.11(A6)
SOC_OSPI0_D5: R95.1 U80.12(A7)
SOC_OSPI0_D6: R96.1 U80.13(A8)
SOC_OSPI0_D7: R97.1 U80.14(A9)
SOC_OSPI0_DQS: U80.15(A10) ; also on sheet 26
SOC_OSPI0_LBCLK: U80.16(A11) ; also on sheet 26
uSD_LS_EN: U22.4(Y) U23.3(ON)
VSYS_3V3_LDO1: C157.1 C158.1 C159.2 C160.1 C161.1 C162.1 C163.1 C164.2 C166.1 C3743.1 C3744.1 C3745.1 R84.1 R85.1 R86.1 R100.2 R101.2 R102.1 R103.2 R104.2 R105.2 R106.2 R107.2 R108.2 R109.1 R111.2 R120.2 R121.2 R1667.2 R1668.2 R1678.2 R1679.2 R3878.2 R3882.1 U18.8(VCC) U19.B4(VCC) U19.D1(VCCQ) U19.E4(VCCQ) U21.5(VCC) U80.1(VCC) U80.17(VCC) U80.30(VCC) ; also on sheet 1 6 7 9 10 11 12 13 14 15 16 17 26 27 28 29 30 32 33
VSYS_3V3_LDO2: C167.1 C168.1 R124.2 R125.2 R127.1 R128.1 R129.1 R130.1 R131.1 R132.1 R133.1 U22.5(VCC) U23.1(VIN) U24.10(VCC) ; also on sheet 1 9 12 13 26 30
WARMRESETn: R126.1 ; also on sheet 12 27
WARMRESETn_R: R126.2 U22.1(A)
N34603287: R90.2 U1.N1(OSPI0_D0)
N34603290: R91.2 U1.N4(OSPI0_D1)
N34603328: R97.2 U1.K1(OSPI0_D7)
N34603356: R87.2 U1.N2(OSPI0_CLK)
N34603584: R92.2 U1.M4(OSPI0_D2)
N34603591: R93.2 U1.P3(OSPI0_D3)
N34800889: R94.2 U1.M1(OSPI0_D4)
N34800895: R96.2 U1.L2(OSPI0_D6)
N35230144: R439.1 U18.5(DI/IO0)
N35230147: R440.1 U18.2(DO/IO1)
N35230153: R442.1 U18.7(~{HOLD}/IO3)
N35244293: R452.1 U19.D2(DQ1)
N35244332: R453.1 U19.C4(DQ2/W#)
N35244360: R454.1 U19.D4(DQ3)
N35244387: R455.1 U19.D5(DQ4)
N35244414: R456.1 U19.E3(DQ5)
N35244441: R457.1 U19.E2(DQ6)
N35244468: R458.1 U19.E1(DQ7)
N35248046: R451.1 U19.D3(DQ0)
N35252647: R441.1 U18.3(~{WP}/IO2)
N35387809: R1678.1 U80.8(EN)

Not connected (* = marked no-connect by the designer): U19 A2(RFU1)* A3(RFU2)* B1(RFU3)* B5(DNU/PSC)* C5(VPP/W#)*; U23 4(CT)*; U24 4(NC1)* 9(NC2)*; U25 1(VCC)* 2(NC)* 3(IO1)*; U80 7(A5)* 19(B11)* 21(B10)* 23(B9)* 25(B8)* 27(B7)* 29(B6)* 31(C5)* 32(B5)*

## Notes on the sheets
sheet 18
- AM263P CC SIP
- PROC159B(002)
- TABLE OF CONTENTS
- CONTENTS
- PAGE
- 01
- TABLE OF CONTENTS
- 02
- REVISION HISTORY
- 03
- SYSTEM BLOCK DIAGRAM
- 04
- POWER FLOW DIAGRAM
- 05
- POWER SEQUENCING
- 06
- I2C TREE
- 07
- GPIO_MAPPING_TABLE
- 08
- POWER INPUT
- PMIC
- 09
- 10
- POWER SUPPLY #1
- CURRENT MONITORING DEVICES
- 11
- 12
- ETHERNET POWERS
- 13
- SOC-POWER and GND
- 14
- SOC-QSPI & OSPI INTERFACE
- 15
- SOC-MMC0 INTERFACE
- 16
- SOC-IO INTERFACES
- 17
- SOC-JTAG, RESET and CLK
- 18
- MCAN AND FSI MUX
- 19
- SOC-PRU0 ICSS MII0,
  CPSW RGMII/MII Ethernet
- 20
- SOC-PRU1 ICSS MII1 Ethernet
- 21
- ICSS ETHERNET/HSEC  MUXES
- 22
- ICSS ON-BOARD/ADD-ON PHY & MII0/MII1 MUXES
- 23
- CLOCKS AND LIN1
- TEST AUTOMATION HEADER
- 24
- 25
- BOOTMODE BUFFER AND SWITCH
- XDS110 DEBUGGER
- 26
- 27
- AUTOMATION SIGNALS BUFFER
- LED DRIVER AND IO EXPANDER
- 28
- 29
- SOC-ADC & DAC INTERFACE
- 30
- ADC MUXES
- 31
- HSEC CONNECTOR
- 32
- RESET SWITCHES
- 33
- CC EVM NOTES, HW and LABELS
sheet 19
- REVISION HISTORY
- VER #
- DATE
- DESCRIPTION OF CHANGES
- AUTHOR
- REVIEWED  BY
- APPROVED  BY
- Drafted from REV A Schematics. Changed Boost converter U5 with part# TPS61089RNRR and
  changed  Q21 (OSPI Reset) from N Channel Fet to P channel FET. Changed U76 Standard PUSH
  PULL OUTPUT Buffer to OPEN DRAIN OUTPUT BUFFER
- 0.01
- 3 FEB 2025
- Mistral Design Team
- 0.02
- Updated System Block Diagram and SOC part number
- 11 APR 2025
- Mistral Design Team
- 0.03
- 0.04
sheet 20
- SYSTEM BLOCK DIAGRAM
sheet 21
- POWER FLOW DIAGRAM
sheet 22
- I2C TREE DIAGRAM
sheet 23
- GPIO MAPPING TABLE
sheet 24
- SOC - QSPI & OSPI Interface
- For SIP
- CAD Note: Place 0-ohm resistors as
  close To SoC as possible.
- NOTE:RST pin is not present in WSON
- CAD NOTE: PLACE 22 OHM SERIES TERMINATION RESISTORS AS CLOSE AS POSSIBLE TO QSPI DEVICE
- OSPI/ QSPI MUX
- CAD NOTE: Place the TPs on OSPI/QSPI lines with minimum stub
- CAD NOTE: PLACE 22 OHM SERIES TERMINATION RESISTORS AS CLOSE AS POSSIBLE TO OSPI DEVICE
- CAD NOTE: PLACE R114
  close to the Memory
  to avoid stub
- OSPI FLASH RESET
- CAD NOTE: Place the resistors close to SOC as possible
- BOOTMODES
- SEL 1 & 2
- CONDITION
- FUNCTION
- LOW
- QSPI SELECTED
- A-->B port
- HIGH
- OSPI selected
- A-->C port
- For SIP
- Note: 10K resistors are used to
  isolate the BOOTMODE control logic
  after the value is latched.
sheet 25
- SOC- MMC0 Interface
- NOTE: WP pin not present in the micro SD
  card conn,
- CAD NOTE: Place the resistors with minimum stub
- MMC0:
- MMC_SD RESET
- Load Switch
- uSD Card Connector
- Silk: uSD CARD CONN
- Place near SD Card Connector
